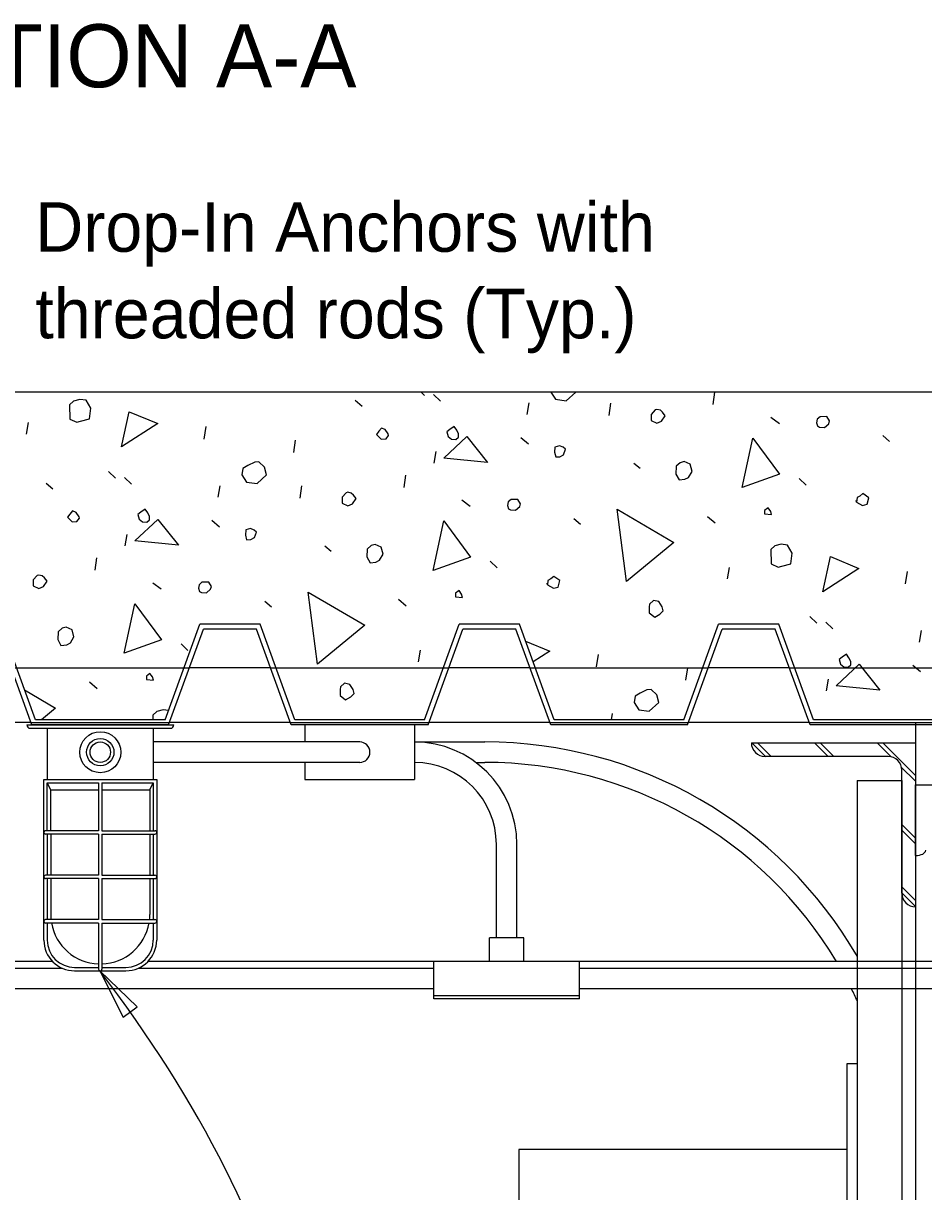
# Model space of a CAD drawing. Extents: x 0 to 30.8, y 0 to 21.2.
# Drawn here: x 15.11 to 17.853, y 6.096 to 9.659 of the extents above; entities that cross this region are included whole.
import ezdxf

# ---------------------------------------------------------------- set-up
doc = ezdxf.new("R2010")
doc.units = 0
for name, color, linetype in [('Dimension', 7, 'Continuous'), ('Lighting', 7, 'Continuous'), ('Lighting_h', 7, 'Continuous'), ('Miscellaneous', 7, 'Continuous'), ('SteelGirder', 7, 'Continuous'), ('SteelGirder_h', 7, 'Continuous'), ('SupstrConc', 7, 'Continuous'), ('TextStructures', 7, 'Continuous')]:
    doc.layers.add(name, color=color, linetype=linetype)

msp = doc.modelspace()

# ---------------------------------------------------------------- linework, layer by layer
at = {"layer": 'Dimension'}
msp.add_lwpolyline([(15.3424, 6.7696), (15.414, 6.6283), (15.4566, 6.6598)], close=True, dxfattribs=at)
msp.add_ellipse((14.9763, 6.3138), major_axis=(-0.8636, 1.2185), ratio=0.378675, start_param=2.874358, end_param=4.819841, dxfattribs=at)
at = {"layer": 'Lighting'}
for p, q in [((15.1203, 7.5197), (15.5682, 7.5197)), ((15.1828, 7.5197), (15.5057, 7.5197)), ((16.3013, 7.5197), (15.968, 7.5197)), ((15.968, 7.5197), (15.968, 7.4676)), ((16.3013, 7.5197), (16.3013, 7.353)), ((15.1307, 7.5093), (15.5578, 7.5093)), ((15.1828, 7.5093), (15.1828, 7.353)), ((15.5057, 7.5093), (15.5057, 7.353)), ((16.1347, 7.4676), (15.5057, 7.4676)), ((16.3013, 7.4676), (16.5159, 7.4676)), ((16.1347, 7.4051), (15.5057, 7.4051)), ((15.968, 7.4051), (15.968, 7.353)), ((16.4888, 7.4051), (16.5159, 7.4051)), ((15.1724, 6.8634), (15.1724, 7.353)), ((15.1724, 7.353), (15.1828, 7.353)), ((15.1828, 7.353), (15.5057, 7.353)), ((15.1828, 7.1968), (15.1828, 7.3426)), ((15.1828, 7.3426), (15.339, 7.3426)), ((15.1932, 7.3218), (15.1828, 7.3426)), ((15.339, 7.3426), (15.339, 7.1968)), ((15.3494, 7.3426), (15.5057, 7.3426)), ((15.3494, 7.3426), (15.3494, 7.1968)), ((15.4953, 7.3218), (15.5057, 7.3426)), ((15.5057, 7.353), (15.5161, 7.353)), ((15.5057, 7.3426), (15.5057, 7.1968)), ((15.5161, 7.353), (15.5161, 6.8634)), ((15.968, 7.353), (16.3013, 7.353)), ((17.6513, 7.3502), (17.6513, 6.4871)), ((17.6513, 7.3502), (17.7867, 7.3502)), ((17.7867, 7.3502), (17.7867, 2.9127)), ((15.1932, 7.3218), (15.339, 7.3218)), ((15.3494, 7.3218), (15.4953, 7.3218)), ((15.339, 7.1968), (15.1776, 7.1968)), ((15.3494, 7.1968), (15.5109, 7.1968)), ((15.339, 7.1864), (15.1776, 7.1864)), ((15.1828, 7.1864), (15.1828, 7.0613)), ((15.339, 7.1864), (15.339, 7.0613)), ((15.3494, 7.1864), (15.5109, 7.1864)), ((15.3494, 7.1864), (15.3494, 7.0613)), ((15.5057, 7.1864), (15.5057, 7.0613)), ((16.5513, 6.8701), (16.5513, 7.1551)), ((16.6138, 6.8701), (16.6138, 7.1551)), ((15.339, 7.0613), (15.1776, 7.0613)), ((15.3494, 7.0613), (15.5109, 7.0613)), ((15.339, 7.0509), (15.1776, 7.0509)), ((15.1828, 7.0509), (15.1828, 6.9259)), ((15.339, 7.0509), (15.339, 6.9259)), ((15.3494, 7.0509), (15.5109, 7.0509)), ((15.3494, 7.0509), (15.3494, 6.9259)), ((15.5057, 7.0509), (15.5057, 6.9259)), ((15.339, 6.9259), (15.1776, 6.9259)), ((15.339, 6.9155), (15.1776, 6.9155)), ((15.1828, 6.9155), (15.1828, 6.8634)), ((15.339, 6.9155), (15.339, 6.7749)), ((15.3494, 6.9259), (15.5109, 6.9259)), ((15.3494, 6.9155), (15.5109, 6.9155)), ((15.3494, 6.9155), (15.3494, 6.7749)), ((15.5057, 6.9155), (15.5057, 6.8634)), ((16.6346, 6.8701), (16.5305, 6.8701)), ((16.5305, 6.798), (16.5305, 6.8701)), ((16.6346, 6.798), (16.6346, 6.8701)), ((15.199, 6.798), (14.4438, 6.798)), ((15.2293, 6.7772), (14.4438, 6.7772)), ((15.2661, 6.7801), (15.339, 6.7801)), ((15.2661, 6.7697), (15.4224, 6.7697)), ((15.3494, 6.7801), (15.4224, 6.7801)), ((16.3605, 6.7772), (15.4592, 6.7772)), ((16.3887, 6.798), (15.4895, 6.798)), ((16.3605, 6.6838), (16.3605, 6.798)), ((17.6513, 6.798), (16.3605, 6.798)), ((16.8047, 6.6838), (16.8047, 6.798)), ((17.6513, 6.7772), (16.8047, 6.7772)), ((16.3605, 6.7147), (14.4438, 6.7147)), ((17.6513, 6.7147), (16.8047, 6.7147)), ((16.8047, 6.6939), (16.3605, 6.6939)), ((16.8047, 6.6838), (16.3605, 6.6838))]:
    msp.add_line(p, q, dxfattribs=at)
msp.add_lwpolyline([(17.6201, 3.4996), (17.6201, 6.2246), (16.6201, 6.2246), (16.6201, 3.4996), (17.5576, 3.4996)], dxfattribs=at)
for radius in [0.0625, 0.0417, 0.0312]:
    msp.add_circle((15.3442, 7.4363), radius, dxfattribs=at)
for centre, radius, start, end in [((15.1307, 7.5197), 0.0104, 180, 270), ((15.5578, 7.5197), 0.0104, 270, 0), ((16.1347, 7.4363), 0.0312, 270, 90), ((16.3013, 7.1551), 0.3125, 0, 90), ((16.5159, 6.1551), 1.3125, 30.1068, 90), ((16.3013, 7.1551), 0.25, 0, 90), ((16.5159, 6.1551), 1.25, 30.9531, 90), ((15.1776, 7.1916), 0.0052, 89.9999, 270), ((15.5109, 7.1916), 0.0052, 270, 90.0001), ((15.1776, 7.0561), 0.0052, 89.9999, 270), ((15.5109, 7.0561), 0.0052, 270, 90.0001), ((15.1776, 6.9207), 0.0052, 89.9999, 270), ((15.5109, 6.9207), 0.0052, 270, 90.0001), ((15.2661, 6.8634), 0.0937, 180, 270), ((15.2661, 6.8634), 0.0833, 180, 270), ((15.4224, 6.8634), 0.0833, 270, 360), ((15.4224, 6.8634), 0.0937, 270, 360), ((15.3442, 6.7749), 0.0052, 179.9665, 0), ((16.5159, 6.1551), 1.25, 24.7221, 26.596)]:
    msp.add_arc(centre, radius, start, end, dxfattribs=at)
at = {"layer": 'Lighting_h'}
for p, q in [((18.2451, 6.798), (17.6513, 6.798)), ((18.2451, 6.7772), (17.6513, 6.7772)), ((18.2451, 6.7147), (17.6513, 6.7147))]:
    msp.add_line(p, q, dxfattribs=at)
at = {"layer": 'Miscellaneous'}
for p, q in [((16.321, 8.5353), (16.3322, 8.5244)), ((16.3601, 8.5267), (16.381, 8.5065)), ((17.212, 8.4962), (17.2175, 8.5339)), ((16.1214, 8.5094), (16.1418, 8.4915)), ((16.6455, 8.466), (16.6516, 8.5013)), ((16.8948, 8.463), (16.9002, 8.5006)), ((17.3879, 8.4579), (17.4137, 8.4389)), ((15.1189, 8.4064), (15.125, 8.4417)), ((15.6613, 8.3913), (15.6668, 8.429)), ((15.9337, 8.3504), (15.9391, 8.3881)), ((16.6255, 8.396), (16.6489, 8.3763)), ((17.7291, 8.4018), (17.7494, 8.3839)), ((16.3618, 8.3175), (16.3679, 8.3528)), ((16.97, 8.3175), (16.9897, 8.302)), ((15.3695, 8.2924), (15.3905, 8.2721)), ((15.4183, 8.2744), (15.4393, 8.2541)), ((16.2702, 8.2438), (16.2757, 8.2815)), ((17.4741, 8.2714), (17.4951, 8.2511)), ((15.1797, 8.257), (15.2, 8.2392)), ((15.7037, 8.2137), (15.7098, 8.249)), ((15.953, 8.2106), (15.9585, 8.2483)), ((16.4461, 8.2056), (16.4719, 8.1866)), ((15.6837, 8.1436), (15.7071, 8.124)), ((16.7873, 8.1494), (16.8076, 8.1316)), ((17.1947, 8.1551), (17.2181, 8.1355)), ((15.42, 8.0652), (15.4261, 8.1005)), ((16.0283, 8.0651), (16.0479, 8.0497)), ((15.3285, 7.9915), (15.3339, 8.0292)), ((16.5324, 8.019), (16.5533, 7.9988)), ((17.2561, 7.9645), (17.2622, 7.9998)), ((17.7985, 7.9494), (17.804, 7.987)), ((15.5044, 7.9532), (15.5302, 7.9342)), ((15.8455, 7.8971), (15.8658, 7.8792)), ((16.2529, 7.9027), (16.2763, 7.8831)), ((17.5067, 7.8504), (17.5277, 7.8302)), ((15.1359, 7.5197), (15.0297, 7.8114)), ((15.1469, 7.5353), (15.0407, 7.827)), ((15.5416, 7.5353), (15.6478, 7.827)), ((15.5525, 7.5197), (15.6587, 7.8114)), ((15.8311, 7.827), (15.6478, 7.827)), ((15.8202, 7.8114), (15.6587, 7.8114)), ((15.9264, 7.5197), (15.8202, 7.8114)), ((15.9373, 7.5353), (15.8311, 7.827)), ((16.3321, 7.5353), (16.4382, 7.827)), ((16.343, 7.5197), (16.4492, 7.8114)), ((16.6215, 7.827), (16.4382, 7.827)), ((16.6106, 7.8114), (16.4492, 7.8114)), ((16.7168, 7.5197), (16.6106, 7.8114)), ((16.7277, 7.5353), (16.6215, 7.827)), ((17.1225, 7.5353), (17.2287, 7.827)), ((17.1334, 7.5197), (17.2396, 7.8114)), ((17.412, 7.827), (17.2287, 7.827)), ((17.4011, 7.8114), (17.2396, 7.8114)), ((17.5073, 7.5197), (17.4011, 7.8114)), ((17.5182, 7.5353), (17.412, 7.827)), ((17.5555, 7.8325), (17.5765, 7.8122)), ((17.8409, 7.7718), (17.847, 7.8071)), ((15.5906, 7.7667), (15.6115, 7.7464)), ((16.3144, 7.7121), (16.3204, 7.7474)), ((16.8568, 7.697), (16.8622, 7.7347)), ((17.8209, 7.7017), (17.8443, 7.6821)), ((17.1291, 7.6561), (17.1346, 7.6938)), ((15.3112, 7.6504), (15.3345, 7.6308)), ((17.5572, 7.6233), (17.5633, 7.6586)), ((16.9019, 7.5353), (16.9052, 7.5547)), ((15.5525, 7.5197), (15.1359, 7.5197)), ((15.5416, 7.5353), (15.1469, 7.5353)), ((16.343, 7.5197), (15.9264, 7.5197)), ((16.3321, 7.5353), (15.9373, 7.5353)), ((17.1334, 7.5197), (16.7168, 7.5197)), ((17.1225, 7.5353), (16.7277, 7.5353)), ((17.9239, 7.5197), (17.5073, 7.5197)), ((17.9129, 7.5353), (17.5182, 7.5353)), ((17.3713, 7.4231), (17.3296, 7.4648)), ((17.389, 7.4231), (17.3473, 7.4648)), ((17.5622, 7.4231), (17.5205, 7.4648)), ((17.5799, 7.4231), (17.5382, 7.4648)), ((17.7555, 7.4207), (17.7115, 7.4648)), ((17.8284, 7.3655), (17.7291, 7.4648)), ((17.8284, 7.3478), (17.7841, 7.3921)), ((15.1932, 7.1968), (15.1932, 7.3218)), ((15.4953, 7.3218), (15.4953, 7.1968)), ((17.8284, 7.1746), (17.7867, 7.2162)), ((17.8284, 7.1569), (17.7867, 7.1986)), ((15.1932, 7.1864), (15.1932, 7.0613)), ((15.4953, 7.1864), (15.4953, 7.0613)), ((15.1932, 7.0509), (15.1932, 6.9415)), ((15.4953, 7.0509), (15.4953, 6.9415)), ((17.8284, 6.9837), (17.7867, 7.0253)), ((17.8284, 6.966), (17.7867, 7.0076))]:
    msp.add_line(p, q, dxfattribs=at)
for points in [[(16.7177, 8.5346), (16.7315, 8.5124), (16.7637, 8.508), (16.793, 8.534), (16.7926, 8.5353)], [(16.7179, 8.5353), (16.7177, 8.5346)], [(15.2502, 8.4959), (15.2516, 8.4523), (15.2724, 8.4423), (15.2844, 8.4456), (15.311, 8.4527), (15.3153, 8.4849), (15.301, 8.5095), (15.2821, 8.5122), (15.2628, 8.5071), (15.2502, 8.4959)], [(17.0233, 8.4663), (17.023, 8.4481), (17.0407, 8.4399), (17.0546, 8.4462), (17.0658, 8.4622), (17.0578, 8.473), (17.051, 8.4789), (17.0401, 8.4812), (17.0352, 8.4799), (17.0233, 8.4663)], [(15.4089, 8.3676), (15.4319, 8.4747), (15.5192, 8.4386), (15.4089, 8.3676)], [(17.5297, 8.4312), (17.5358, 8.4276), (17.5516, 8.4267), (17.5641, 8.4378), (17.567, 8.4464), (17.5583, 8.4596), (17.5377, 8.4592), (17.5293, 8.4518), (17.5271, 8.4408), (17.5297, 8.4312)], [(16.1857, 8.4049), (16.1999, 8.3906), (16.215, 8.3921), (16.2227, 8.4019), (16.2214, 8.4067), (16.2127, 8.4199), (16.2011, 8.4246), (16.1934, 8.4148), (16.1857, 8.4049)], [(16.4047, 8.3989), (16.4145, 8.3912), (16.4279, 8.3896), (16.4363, 8.397), (16.4361, 8.4073), (16.4304, 8.4188), (16.4224, 8.4295), (16.4092, 8.4208), (16.4008, 8.4134), (16.4047, 8.3989)], [(16.3912, 8.3332), (16.4617, 8.3987), (16.5243, 8.3197), (16.3912, 8.3332)], [(17.3006, 8.243), (17.3326, 8.3939), (17.4139, 8.2837), (17.3006, 8.243)], [(16.7281, 8.351), (16.732, 8.3365), (16.7447, 8.3373), (16.7561, 8.343), (16.7619, 8.3601), (16.7551, 8.366), (16.7435, 8.3707), (16.7291, 8.3668), (16.7281, 8.351)], [(15.776, 8.2822), (15.7897, 8.26), (15.8219, 8.2557), (15.8512, 8.2817), (15.8447, 8.3058), (15.8275, 8.3219), (15.8147, 8.3211), (15.7943, 8.3104), (15.7787, 8.3011), (15.776, 8.2822)], [(17.0994, 8.3081), (17.0979, 8.2844), (17.1079, 8.2664), (17.1255, 8.2685), (17.1369, 8.2742), (17.1475, 8.2926), (17.1417, 8.3143), (17.124, 8.3225), (17.1119, 8.3192), (17.0994, 8.3081)], [(16.0815, 8.214), (16.0812, 8.1958), (16.099, 8.1876), (16.1128, 8.1939), (16.1241, 8.2098), (16.116, 8.2206), (16.1092, 8.2266), (16.0983, 8.2288), (16.0934, 8.2275), (16.0815, 8.214)], [(16.5879, 8.1788), (16.594, 8.1753), (16.6098, 8.1744), (16.6223, 8.1855), (16.6252, 8.194), (16.6165, 8.2072), (16.5959, 8.2069), (16.5875, 8.1994), (16.5853, 8.1885), (16.5879, 8.1788)], [(17.6488, 8.1991), (17.6672, 8.1885), (17.6817, 8.1924), (17.6868, 8.2119), (17.6678, 8.2249), (17.6594, 8.2175), (17.6504, 8.2125), (17.6488, 8.1991), (17.6475, 8.2039)], [(15.2439, 8.1526), (15.2581, 8.1383), (15.2732, 8.1397), (15.2809, 8.1496), (15.2796, 8.1544), (15.2709, 8.1676), (15.2593, 8.1723), (15.2516, 8.1624), (15.2439, 8.1526)], [(15.4629, 8.1466), (15.4727, 8.1389), (15.4861, 8.1373), (15.4945, 8.1447), (15.4943, 8.155), (15.4887, 8.1664), (15.4806, 8.1772), (15.4674, 8.1685), (15.459, 8.1611), (15.4629, 8.1466)], [(16.9476, 7.9569), (16.9196, 8.1771), (17.0917, 8.0757), (16.9476, 7.9569)], [(17.3686, 8.1629), (17.3899, 8.1608), (17.3873, 8.1705), (17.3792, 8.1812), (17.3685, 8.1732), (17.3686, 8.1629)], [(15.4495, 8.0808), (15.5199, 8.1463), (15.5825, 8.0673), (15.4495, 8.0808)], [(16.3588, 7.9906), (16.3908, 8.1416), (16.4721, 8.0313), (16.3588, 7.9906)], [(15.7863, 8.0986), (15.7902, 8.0842), (15.8029, 8.085), (15.8144, 8.0906), (15.8201, 8.1077), (15.8134, 8.1137), (15.8018, 8.1183), (15.7873, 8.1144), (15.7863, 8.0986)], [(16.1576, 8.0558), (16.1562, 8.0321), (16.1662, 8.0141), (16.1837, 8.0162), (16.1951, 8.0218), (16.2058, 8.0402), (16.1999, 8.0619), (16.1822, 8.0701), (16.1701, 8.0669), (16.1576, 8.0558)], [(17.3874, 8.054), (17.3888, 8.0104), (17.4096, 8.0004), (17.4216, 8.0037), (17.4482, 8.0108), (17.4525, 8.043), (17.4382, 8.0676), (17.4193, 8.0703), (17.4, 8.0651), (17.3874, 8.054)], [(17.5461, 7.9257), (17.5691, 8.0328), (17.6564, 7.9967), (17.5461, 7.9257)], [(15.1398, 7.9616), (15.1395, 7.9434), (15.1572, 7.9352), (15.171, 7.9415), (15.1823, 7.9575), (15.1742, 7.9683), (15.1674, 7.9742), (15.1565, 7.9765), (15.1517, 7.9752), (15.1398, 7.9616)], [(15.6461, 7.9265), (15.6522, 7.923), (15.668, 7.922), (15.6806, 7.9331), (15.6835, 7.9417), (15.6747, 7.9549), (15.6541, 7.9545), (15.6458, 7.9471), (15.6435, 7.9361), (15.6461, 7.9265)], [(16.707, 7.9468), (16.7254, 7.9362), (16.7399, 7.94), (16.745, 7.9595), (16.726, 7.9725), (16.7176, 7.9651), (16.7086, 7.9601), (16.707, 7.9468), (16.7057, 7.9516)], [(16.0058, 7.7045), (15.9779, 7.9248), (16.15, 7.8234), (16.0058, 7.7045)], [(16.4269, 7.9105), (16.4481, 7.9084), (16.4455, 7.9181), (16.4375, 7.9289), (16.4267, 7.9208), (16.4269, 7.9105)], [(15.417, 7.7383), (15.449, 7.8892), (15.5303, 7.779), (15.417, 7.7383)], [(17.0174, 7.8798), (17.0171, 7.8616), (17.0337, 7.8479), (17.0493, 7.8573), (17.0595, 7.8678), (17.0562, 7.8799), (17.0469, 7.8955), (17.0304, 7.8988), (17.0179, 7.8877), (17.0174, 7.8798)], [(15.2158, 7.8034), (15.2144, 7.7797), (15.2244, 7.7617), (15.2419, 7.7638), (15.2534, 7.7695), (15.264, 7.7879), (15.2582, 7.8096), (15.2404, 7.8178), (15.2284, 7.8145), (15.2158, 7.8034)], [(16.6405, 7.775), (16.7147, 7.7443), (16.6636, 7.7115)], [(17.6001, 7.7047), (17.6099, 7.6969), (17.6233, 7.6953), (17.6317, 7.7028), (17.6315, 7.7131), (17.6259, 7.7245), (17.6178, 7.7353), (17.6046, 7.7266), (17.5962, 7.7191), (17.6001, 7.7047)], [(17.5867, 7.6389), (17.6571, 7.7044), (17.7197, 7.6254), (17.5867, 7.6389)], [(15.4851, 7.6582), (15.5063, 7.6561), (15.5037, 7.6658), (15.4957, 7.6765), (15.4849, 7.6685), (15.4851, 7.6582)], [(15.1136, 7.6268), (15.2082, 7.571), (15.1648, 7.5353)], [(16.0756, 7.6275), (16.0753, 7.6093), (16.0919, 7.5956), (16.1076, 7.605), (16.1177, 7.6154), (16.1145, 7.6275), (16.1051, 7.6431), (16.0887, 7.6465), (16.0761, 7.6354), (16.0756, 7.6275)], [(16.9714, 7.588), (16.9851, 7.5658), (17.0173, 7.5614), (17.0466, 7.5874), (17.0401, 7.6116), (17.0229, 7.6276), (17.0102, 7.6268), (16.9897, 7.6162), (16.9741, 7.6068), (16.9714, 7.588)], [(15.5518, 7.5633), (15.5358, 7.5656), (15.5164, 7.5604), (15.5039, 7.5493)], [(15.5039, 7.5493), (15.5043, 7.5353)]]:
    msp.add_lwpolyline(points, dxfattribs=at)
for start, end in [(180, 185.9203), (189.9053, 268.0265), (271.9735, 350.0947), (354.0797, 0)]:
    msp.add_arc((15.3442, 6.9415), 0.151, start, end, dxfattribs=at)
at = {"layer": 'SteelGirder'}
for p, q in [((15.8629, 7.694), (15.616, 7.694)), ((16.6534, 7.694), (16.4064, 7.694)), ((17.4438, 7.694), (17.1969, 7.694)), ((15.1332, 7.5273), (14.7649, 7.5273)), ((15.9236, 7.5273), (15.5553, 7.5273)), ((16.714, 7.5273), (16.3458, 7.5273)), ((17.5045, 7.5273), (17.1362, 7.5273)), ((17.8284, 7.5273), (17.8284, 7.4648)), ((17.3284, 7.4648), (17.8284, 7.4648)), ((17.8284, 7.4648), (17.8284, 6.9648)), ((17.7451, 7.4231), (17.3701, 7.4231)), ((17.7867, 7.0064), (17.7867, 7.3814)), ((17.8284, 7.1211), (17.8284, 7.3368)), ((17.8284, 7.3368), (18.2451, 7.3368)), ((17.8284, 6.9648), (17.8284, 2.0794))]:
    msp.add_line(p, q, dxfattribs=at)
msp.add_lwpolyline([(17.6201, 6.4871), (17.6513, 6.4871), (17.6513, 3.2371), (17.6201, 3.2371)], close=True, dxfattribs=at)
for centre, start, end in [((17.3701, 7.4648), 180, 270), ((17.7451, 7.3814), 0, 90), ((17.8284, 7.0064), 180, 270)]:
    msp.add_arc(centre, 0.0417, start, end, dxfattribs=at)
msp.add_ellipse((17.8284, 7.1373), major_axis=(0.0312, 0), ratio=0.5176, start_param=4.712389, end_param=6.283185, dxfattribs=at)
at = {"layer": 'SteelGirder_h'}
for p, q in [((15.0725, 7.694), (15.616, 7.694)), ((15.8629, 7.694), (16.4064, 7.694)), ((16.6534, 7.694), (17.1969, 7.694)), ((17.4438, 7.694), (17.9873, 7.694)), ((15.1332, 7.5273), (15.5553, 7.5273)), ((15.9236, 7.5273), (16.3458, 7.5273)), ((16.714, 7.5273), (17.1362, 7.5273)), ((17.5045, 7.5273), (17.9266, 7.5273))]:
    msp.add_line(p, q, dxfattribs=at)
at = {"layer": 'SupstrConc'}
msp.add_line((13.7516, 8.5353), (20.7608, 8.5353), dxfattribs=at)

# ---------------------------------------------------------------- texts
at = {"layer": 'Dimension'}
for s, p in [('Drop-In Anchors with', (15.1464, 8.9623)), ('threaded rods (Typ.)', (15.1464, 8.6983))]:
    msp.add_text(s, height=0.1512, dxfattribs=at).set_placement(p)
at = {"layer": 'TextStructures'}
msp.add_text('SECTION A-A', height=0.192, dxfattribs=at).set_placement((14.4844, 9.4639))

doc.saveas('drawing.dxf')
